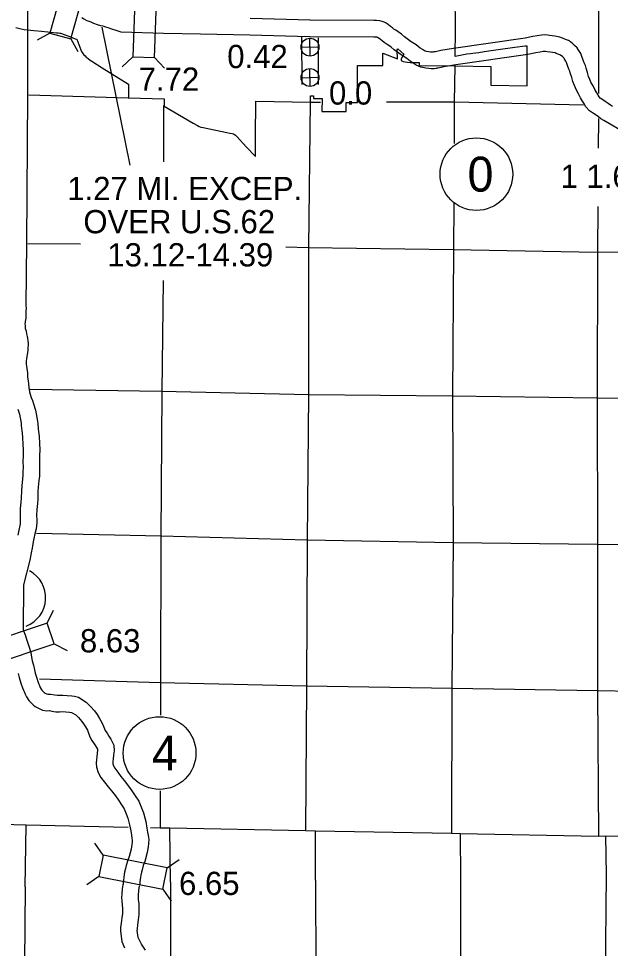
# Model space of a CAD drawing. Extents: x 77230 to 630905, y 790554 to 1662844.
# Drawn here: x 454103 to 475616, y 1547927 to 1581703 of the extents above; entities that cross this region are included whole.
import ezdxf

# ---------------------------------------------------------------- set-up
doc = ezdxf.new("R2010")
doc.units = 0
for name, color, linetype in [('Level 12', 7, 'Continuous'), ('Level 15', 7, 'Continuous'), ('Level 16', 7, 'Continuous'), ('Level 19', 7, 'Continuous'), ('Level 22', 7, 'Continuous'), ('Level 23', 7, 'Continuous'), ('Level 26', 7, 'Continuous'), ('Level 31', 7, 'Continuous'), ('Level 32', 7, 'Continuous'), ('Level 33', 7, 'Continuous'), ('Level 34', 7, 'Continuous')]:
    doc.layers.add(name, color=color, linetype=linetype)

msp = doc.modelspace()

# ---------------------------------------------------------------- linework, layer by layer
at = {"layer": 'Level 12'}
for points in [[(466420, 1578652), (466422, 1579998), (467339, 1579997), (467339, 1580452), (467872, 1580237), (467869, 1580571), (467890, 1580603), (468112, 1580410), (468011, 1580239), (468009, 1580182), (468088, 1580148), (468161, 1580131), (468243, 1580115), (468336, 1580106), (468659, 1580103), (468659, 1579995), (469973, 1579992), (471268, 1579963), (471265, 1579286), (472585, 1579255), (472591, 1580707), (472515, 1580699), (472141, 1580649), (471534, 1580563), (471028, 1580491), (470830, 1580465), (470712, 1580450), (470611, 1580438), (470526, 1580426), (470400, 1580407), (469975, 1580320), (469981, 1581299), (469976, 1582639)], [(454003, 1581377), (454103, 1581350), (454198, 1581329), (454307, 1581310), (454445, 1581292), (454656, 1581273), (454935, 1581246), (455275, 1581211), (455484, 1581191), (455537, 1581186), (455603, 1581178), (455632, 1581172), (455664, 1581162), (455756, 1581129), (455853, 1581092), (455930, 1581063), (456075, 1581006), (456158, 1580973), (456217, 1580951), (456370, 1580574), (456396, 1580513), (456443, 1580434), (456477, 1580390), (456518, 1580348), (456563, 1580305), (456627, 1580253), (456706, 1580196), (456768, 1580156), (457144, 1579910), (458094, 1579317), (458095, 1578819), (459392, 1578785), (459392, 1578772), (459392, 1578523), (460446, 1577908), (460607, 1577819), (460670, 1577787), (460728, 1577763), (460810, 1577745), (461675, 1577568), (461786, 1577544), (461867, 1577525), (461916, 1577511), (461956, 1577488), (461982, 1577468), (462035, 1577414), (462387, 1577027), (462716, 1576691), (462719, 1577403), (462726, 1578705), (464714, 1578665), (464714, 1578902), (464819, 1578901), (464819, 1578802), (465136, 1578799), (465125, 1578331), (466012, 1578322), (466016, 1578652), (466420, 1578652)]]:
    msp.add_lwpolyline(points, dxfattribs=at)
at = {"layer": 'Level 15'}
for points in [[(458090, 1552322), (454382, 1552405), (453934, 1552413), (448822, 1552469), (448732, 1552478), (443610, 1552521), (443540, 1552520), (442266, 1552501)], [(479121, 1551968), (475435, 1552000), (475181, 1551997), (470150, 1552090), (469836, 1552104), (464890, 1552185), (464531, 1552192), (459599, 1552293), (459245, 1552297), (458894, 1552305)]]:
    msp.add_lwpolyline(points, dxfattribs=at)
at = {"layer": 'Level 16'}
for points in [[(475183, 1584049), (475183, 1578982)], [(469957, 1579985), (469940, 1578663), (469933, 1577160)], [(458081, 1578817), (454479, 1578917)], [(459369, 1578547), (459372, 1576499)], [(464697, 1578675), (464638, 1573398), (464644, 1568052), (464593, 1562762), (464570, 1557467), (464531, 1552192)], [(465079, 1578656), (464697, 1578655)], [(474639, 1578558), (469946, 1578667), (467472, 1578661)], [(475180, 1578079), (475172, 1577000)], [(469922, 1575034), (469913, 1573288), (469876, 1568013), (469898, 1562654), (469847, 1557367), (469836, 1552104)], [(475156, 1574873), (475144, 1573241), (475138, 1567916), (475152, 1562591), (475152, 1557269), (475181, 1551997)], [(456356, 1573510), (454440, 1573519)], [(478780, 1573251), (475133, 1573212), (469904, 1573306), (464628, 1573380), (463821, 1573398)], [(459361, 1572185), (459315, 1568159), (459274, 1562888), (459260, 1557586), (459256, 1556404)], [(478860, 1567899), (475138, 1567912), (469864, 1567986), (464658, 1568040), (459295, 1568157), (454530, 1568235)], [(478938, 1562590), (475144, 1562599), (469892, 1562658), (464597, 1562760), (459288, 1562901), (454750, 1562996)], [(479039, 1557211), (475151, 1557287), (469861, 1557367), (464571, 1557455), (459248, 1557573), (454860, 1557710)], [(459249, 1553655), (459245, 1552297)], [(454344, 1550167), (454382, 1552405)], [(459621, 1550335), (459599, 1552293)], [(464897, 1550409), (464890, 1552185)], [(470150, 1552090), (470165, 1550489)], [(475435, 1552000), (475467, 1550607)], [(459621, 1550335), (459631, 1547226), (459599, 1541883), (459606, 1539822)], [(464897, 1550409), (464909, 1547088), (464853, 1541677), (464848, 1536421), (464845, 1530966), (464852, 1529685)], [(470165, 1550489), (470165, 1546976), (470088, 1541571), (470194, 1536276), (470193, 1530873), (470194, 1528109)], [(475467, 1550607), (475421, 1546853), (475426, 1541492), (475472, 1536120), (475443, 1530759), (475462, 1528410)], [(454344, 1550167), (454323, 1547392), (454305, 1541955), (454272, 1539602)]]:
    msp.add_lwpolyline(points, dxfattribs=at)
at = {"layer": 'Level 19'}
for p, q in [((455241, 1581179), (454781, 1580920)), ((456003, 1580965), (456262, 1580505)), ((458257, 1580312), (457871, 1579951)), ((459048, 1580285), (459409, 1579899)), ((455141, 1559737), (455377, 1560209)), ((455392, 1558986), (455864, 1558750)), ((457173, 1551313), (456878, 1551751)), ((459505, 1550856), (459943, 1551151)), ((457021, 1550535), (456583, 1550241)), ((459352, 1550079), (459647, 1549641))]:
    msp.add_line(p, q, dxfattribs=at)
for points in [[(456003, 1580965), (456645, 1583253), (455883, 1583466), (455241, 1581179)], [(458337, 1582687), (458257, 1580312), (459048, 1580285), (459129, 1582660)], [(453138, 1558234), (455392, 1558986), (455141, 1559737), (452887, 1558985)], [(459505, 1550856), (457173, 1551313), (457021, 1550535), (459352, 1550079)]]:
    msp.add_lwpolyline(points, close=True, dxfattribs=at)
at = {"layer": 'Level 22'}
for points in [[(454427, 1582027), (454433, 1578936), (454393, 1573546), (454361, 1571290), (454376, 1571174), (454370, 1571090), (454372, 1571037), (454370, 1570848), (454362, 1570800), (454358, 1570772), (454345, 1570690), (454337, 1570648), (454336, 1570627), (454337, 1570555), (454342, 1570496), (454344, 1570485), (454348, 1570457), (454356, 1570427), (454377, 1570343), (454393, 1570257), (454405, 1570208), (454416, 1570150), (454429, 1570089), (454441, 1569996), (454447, 1569910), (454448, 1569826), (454442, 1569757), (454438, 1569653), (454430, 1569569), (454413, 1569491), (454405, 1569440), (454387, 1569332), (454380, 1569281), (454374, 1569232), (454374, 1569200), (454381, 1569145), (454389, 1569080), (454405, 1568990), (454422, 1568837), (454432, 1568683), (454446, 1568540), (454459, 1568439), (454474, 1568305), (454503, 1568142), (454543, 1567978), (454558, 1567942), (454604, 1567835), (454648, 1567708), (454722, 1567473), (454790, 1567084), (454800, 1566988), (454820, 1566798), (454832, 1566699), (454847, 1566531), (454863, 1566272), (454870, 1566042), (454866, 1565826), (454862, 1565588), (454864, 1565421), (454860, 1565214), (454859, 1565147), (454858, 1565077), (454842, 1564918), (454814, 1564680), (454807, 1564541), (454806, 1564540), (454797, 1564254), (454786, 1564090), (454764, 1563870), (454759, 1563654), (454765, 1563483), (454766, 1563388), (454760, 1563281), (454739, 1563165), (454698, 1562984), (454661, 1562822), (454637, 1562692), (454593, 1562471), (454563, 1562301), (454508, 1562024), (454281, 1561136), (454271, 1559524), (454282, 1559462), (454339, 1559313), (454397, 1559161), (454481, 1558909), (454545, 1558676), (454572, 1558508), (454599, 1558378), (454641, 1558211), (454677, 1558049), (454707, 1557925), (454761, 1557740), (454804, 1557619), (454845, 1557529), (454865, 1557473), (454893, 1557409), (454924, 1557344), (454948, 1557304), (454963, 1557290), (455003, 1557250)], [(464393, 1581043), (464398, 1579309)], [(464993, 1581003), (464998, 1579311)], [(454078, 1567519), (454138, 1567331), (454195, 1567001), (454203, 1566924), (454224, 1566731), (454235, 1566638), (454248, 1566486), (454263, 1566244), (454270, 1566038), (454267, 1565837), (454262, 1565590), (454264, 1565422), (454261, 1565224), (454259, 1565158), (454258, 1565112), (454246, 1564982), (454216, 1564731), (454206, 1564547), (454197, 1564283), (454188, 1564139), (454164, 1563906), (454159, 1563649), (454165, 1563468), (454166, 1563403), (454163, 1563354), (454151, 1563285), (454112, 1563116), (454073, 1562941)], [(454093, 1557914), (454127, 1557771), (454190, 1557556), (454247, 1557394), (454288, 1557305), (454306, 1557254), (454348, 1557158), (454395, 1557060), (454473, 1556929), (454544, 1556860), (454584, 1556821)], [(455008, 1557245), (455029, 1557224), (455068, 1557203), (455099, 1557189), (455161, 1557160), (455260, 1557167), (455424, 1557140), (455517, 1557120), (455579, 1557120), (455711, 1557128), (455872, 1557118), (456033, 1557098), (456131, 1557085), (456283, 1557050), (456565, 1556877), (456718, 1556718), (456864, 1556552), (456956, 1556429), (457049, 1556280), (457147, 1556109), (457205, 1555963), (457252, 1555840), (457269, 1555809), (457321, 1555745), (457387, 1555639), (457459, 1555526), (457519, 1555408), (457563, 1555305), (457572, 1555108), (457558, 1554953), (457540, 1554804), (457529, 1554731), (457526, 1554668), (457529, 1554626), (457553, 1554553), (457600, 1554469), (457705, 1554327), (457823, 1554167), (457946, 1554025), (458104, 1553821), (458223, 1553654), (458345, 1553475), (458470, 1553281), (458573, 1553038), (458643, 1552849), (458697, 1552665), (458726, 1552534), (458771, 1552294), (458795, 1552145), (458817, 1552033), (458837, 1551888), (458831, 1551740), (458814, 1551615), (458781, 1551408), (458695, 1551084), (458637, 1550934), (458590, 1550779), (458569, 1550700), (458547, 1550587), (458533, 1550509), (458522, 1550432), (458511, 1550344), (458507, 1550278), (458507, 1550251)], [(454579, 1556826), (454642, 1556762), (454706, 1556718), (454802, 1556664), (454851, 1556643), (454977, 1556583), (455126, 1556556), (455232, 1556563), (455313, 1556550), (455452, 1556520), (455595, 1556519), (455711, 1556527), (455818, 1556520), (455957, 1556503), (456023, 1556494), (456052, 1556488), (456186, 1556406), (456276, 1556312), (456398, 1556173), (456461, 1556089), (456535, 1555972), (456605, 1555849), (456646, 1555744), (456707, 1555588), (456768, 1555476), (456830, 1555397), (456879, 1555320), (456937, 1555227), (456969, 1555166), (456971, 1555122), (456961, 1555016), (456946, 1554885), (456931, 1554793), (456925, 1554660), (456936, 1554510), (457000, 1554311), (457096, 1554141), (457223, 1553970), (457354, 1553792), (457482, 1553645), (457622, 1553464), (457731, 1553310), (457845, 1553144), (457937, 1553000), (458016, 1552816), (458074, 1552659), (458116, 1552516), (458138, 1552415), (458180, 1552192), (458204, 1552041), (458225, 1551933), (458235, 1551859), (458232, 1551794), (458220, 1551702), (458194, 1551532), (458124, 1551270), (458069, 1551130), (458013, 1550942), (457984, 1550833), (457957, 1550697), (457941, 1550607), (457927, 1550515), (457913, 1550398), (457907, 1550291), (457907, 1550243)], [(457966, 1547941), (457872, 1548166), (457816, 1548564), (457826, 1548692), (457842, 1548848), (457868, 1549043), (457887, 1549196), (457890, 1549385), (457884, 1549499), (457867, 1549653), (457859, 1549776), (457864, 1549900), (457882, 1550103), (457911, 1550292)], [(458520, 1548172), (458455, 1548326), (458419, 1548581), (458424, 1548637), (458438, 1548778), (458463, 1548968), (458487, 1549155), (458490, 1549396), (458482, 1549546), (458465, 1549704), (458460, 1549785), (458463, 1549862), (458478, 1550031), (458504, 1550202)], [(458718, 1547857), (458573, 1548077), (458506, 1548200)]]:
    msp.add_lwpolyline(points, dxfattribs=at)
at = {"layer": 'Level 23'}
for points in [[(460711, 1581132), (459369, 1581163), (457828, 1581215), (457646, 1581265), (457498, 1581317), (457357, 1581366), (457270, 1581395), (457177, 1581424), (457088, 1581445), (456970, 1581480), (456844, 1581530), (456741, 1581572), (456602, 1581625), (456461, 1581698), (456408, 1581732)], [(464700, 1581641), (462525, 1581703)], [(475689, 1578509), (475614, 1578559), (475535, 1578617), (475430, 1578691), (475342, 1578748), (475248, 1578815), (475205, 1578859), (475168, 1578922), (475126, 1579003), (475051, 1579125), (474984, 1579255), (474917, 1579374), (474864, 1579495), (474821, 1579605), (474784, 1579741), (474732, 1579898), (474706, 1579999), (474661, 1580093), (474628, 1580196), (474579, 1580326), (474536, 1580437), (474444, 1580576), (474402, 1580645), (474316, 1580731), (474255, 1580791), (474160, 1580856), (474087, 1580907), (473986, 1580944), (473880, 1580986), (473778, 1581033), (473596, 1581062), (473494, 1581076), (473405, 1581086), (473344, 1581097), (473234, 1581110), (473107, 1581103), (472959, 1581078), (472794, 1581047), (472512, 1580993), (469907, 1580611), (469456, 1580538), (469359, 1580519), (469252, 1580501), (469201, 1580493), (469157, 1580483), (469143, 1580480), (469110, 1580480), (469075, 1580482), (469017, 1580491), (468921, 1580513), (468910, 1580516), (468863, 1580536), (468819, 1580552), (468781, 1580577), (468705, 1580634), (468557, 1580752), (468378, 1580859), (468276, 1580934), (468134, 1581038), (468025, 1581134), (467898, 1581227), (467818, 1581278), (467744, 1581322), (467691, 1581369), (467622, 1581420), (467536, 1581489), (467462, 1581540), (467388, 1581578), (467322, 1581597), (467232, 1581625), (467112, 1581630), (467019, 1581630), (464693, 1581641)], [(462512, 1581103), (460713, 1581132)], [(464683, 1581041), (462508, 1581103)], [(476159, 1577543), (475373, 1577999), (475270, 1578067), (475183, 1578131), (475094, 1578194), (475005, 1578251), (474857, 1578357), (474725, 1578492), (474644, 1578630), (474604, 1578705), (474528, 1578830), (474455, 1578970), (474379, 1579106), (474308, 1579267), (474251, 1579416), (474209, 1579568), (474156, 1579730), (474140, 1579792), (474103, 1579869), (474061, 1579998), (474019, 1580111), (474000, 1580159), (473937, 1580254), (473926, 1580273), (473894, 1580305), (473874, 1580325), (473819, 1580362), (473808, 1580370), (473772, 1580383), (473644, 1580434), (473602, 1580454), (473508, 1580469), (473420, 1580481), (473318, 1580492), (473254, 1580504), (473216, 1580508), (473175, 1580506), (473063, 1580487), (472906, 1580458), (472613, 1580401), (469998, 1580018), (469563, 1579948), (469469, 1579929), (469347, 1579908), (469311, 1579903), (469280, 1579896), (469205, 1579881), (469098, 1579880), (469013, 1579884), (468903, 1579901), (468790, 1579928), (468729, 1579941), (468639, 1579979), (468550, 1580013), (468440, 1580083), (468337, 1580160), (468214, 1580258), (468046, 1580359), (467922, 1580449), (467757, 1580570), (467648, 1580667), (467560, 1580731), (467504, 1580767), (467388, 1580836), (467315, 1580900), (467256, 1580944), (467176, 1581008), (467160, 1581019), (467152, 1581022), (467130, 1581028), (467097, 1581030), (467014, 1581030), (464691, 1581041)]]:
    msp.add_lwpolyline(points, dxfattribs=at)
at = {"layer": 'Level 26'}
msp.add_arc((453988, 1560668), 1100, 290.4926, 62.2658, dxfattribs=at)
at = {"layer": 'Level 31'}
msp.add_line((458162, 1576378), (457138, 1581395), dxfattribs=at)
at = {"layer": 'Level 33'}
for centre in [(470745, 1576052), (459228, 1555024)]:
    msp.add_circle(centre, 1320, dxfattribs=at)
at = {"layer": 'Level 34'}
for p, q in [((464703, 1580341), (464688, 1580992)), ((464370, 1580659), (465021, 1580674)), ((464703, 1579237), (464688, 1579888)), ((464370, 1579555), (465021, 1579570))]:
    msp.add_line(p, q, dxfattribs=at)
for centre in [(464696, 1580666), (464696, 1579563)]:
    msp.add_circle(centre, 326, dxfattribs=at)

# ---------------------------------------------------------------- texts
at = {"layer": 'Level 31'}
for s, p in [('0.42', (461688, 1579903)), ('0.0', (465387, 1578579)), ('1.27 MI. EXCEP.', (455874, 1575108)), ('OVER U.S.62', (456458, 1573904)), ('13.12-14.39', (457330, 1572700))]:
    msp.add_text(s, height=844.8, dxfattribs=at).set_placement(p)
at = {"layer": 'Level 32'}
for s, p in [('7.72', (458469, 1579080)), ('1 1.68', (473802, 1575549)), ('8.63', (456334, 1558680)), ('6.65', (459936, 1549867))]:
    msp.add_text(s, height=844.8, dxfattribs=at).set_placement(p)
at = {"layer": 'Level 33'}
for s, p in [('0', (470422, 1575418)), ('4', (458945, 1554391))]:
    msp.add_text(s, height=1267, dxfattribs=at).set_placement(p)

doc.saveas('drawing.dxf')
